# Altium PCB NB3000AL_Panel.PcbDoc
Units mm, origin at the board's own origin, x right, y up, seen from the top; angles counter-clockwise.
Board outline 262 x 196.02 mm, 6 copper layers (Top Layer, GND+SHIELD, MidLayer1, MidLayer2, P2 - 3V3+5V0, Bottom Layer); 0 components, 0 nets, 91 pads, 0 vias.
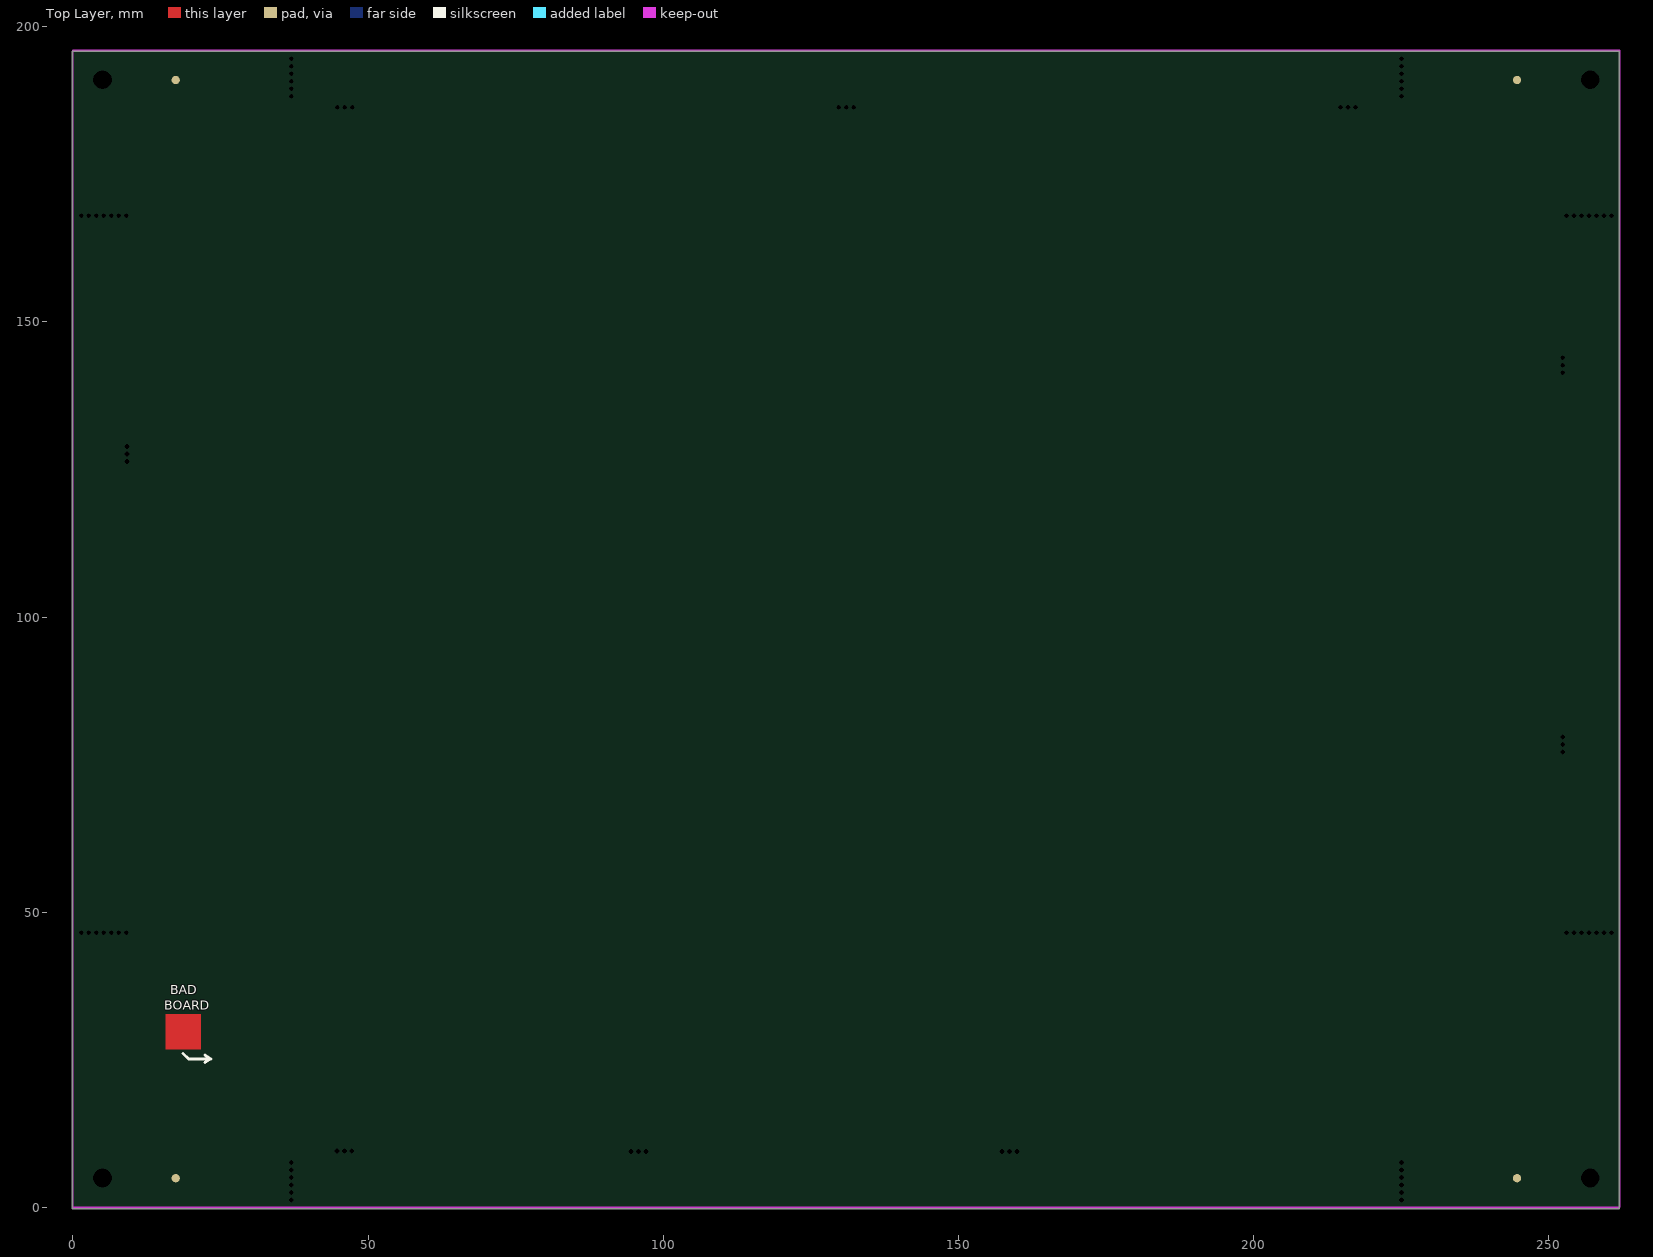
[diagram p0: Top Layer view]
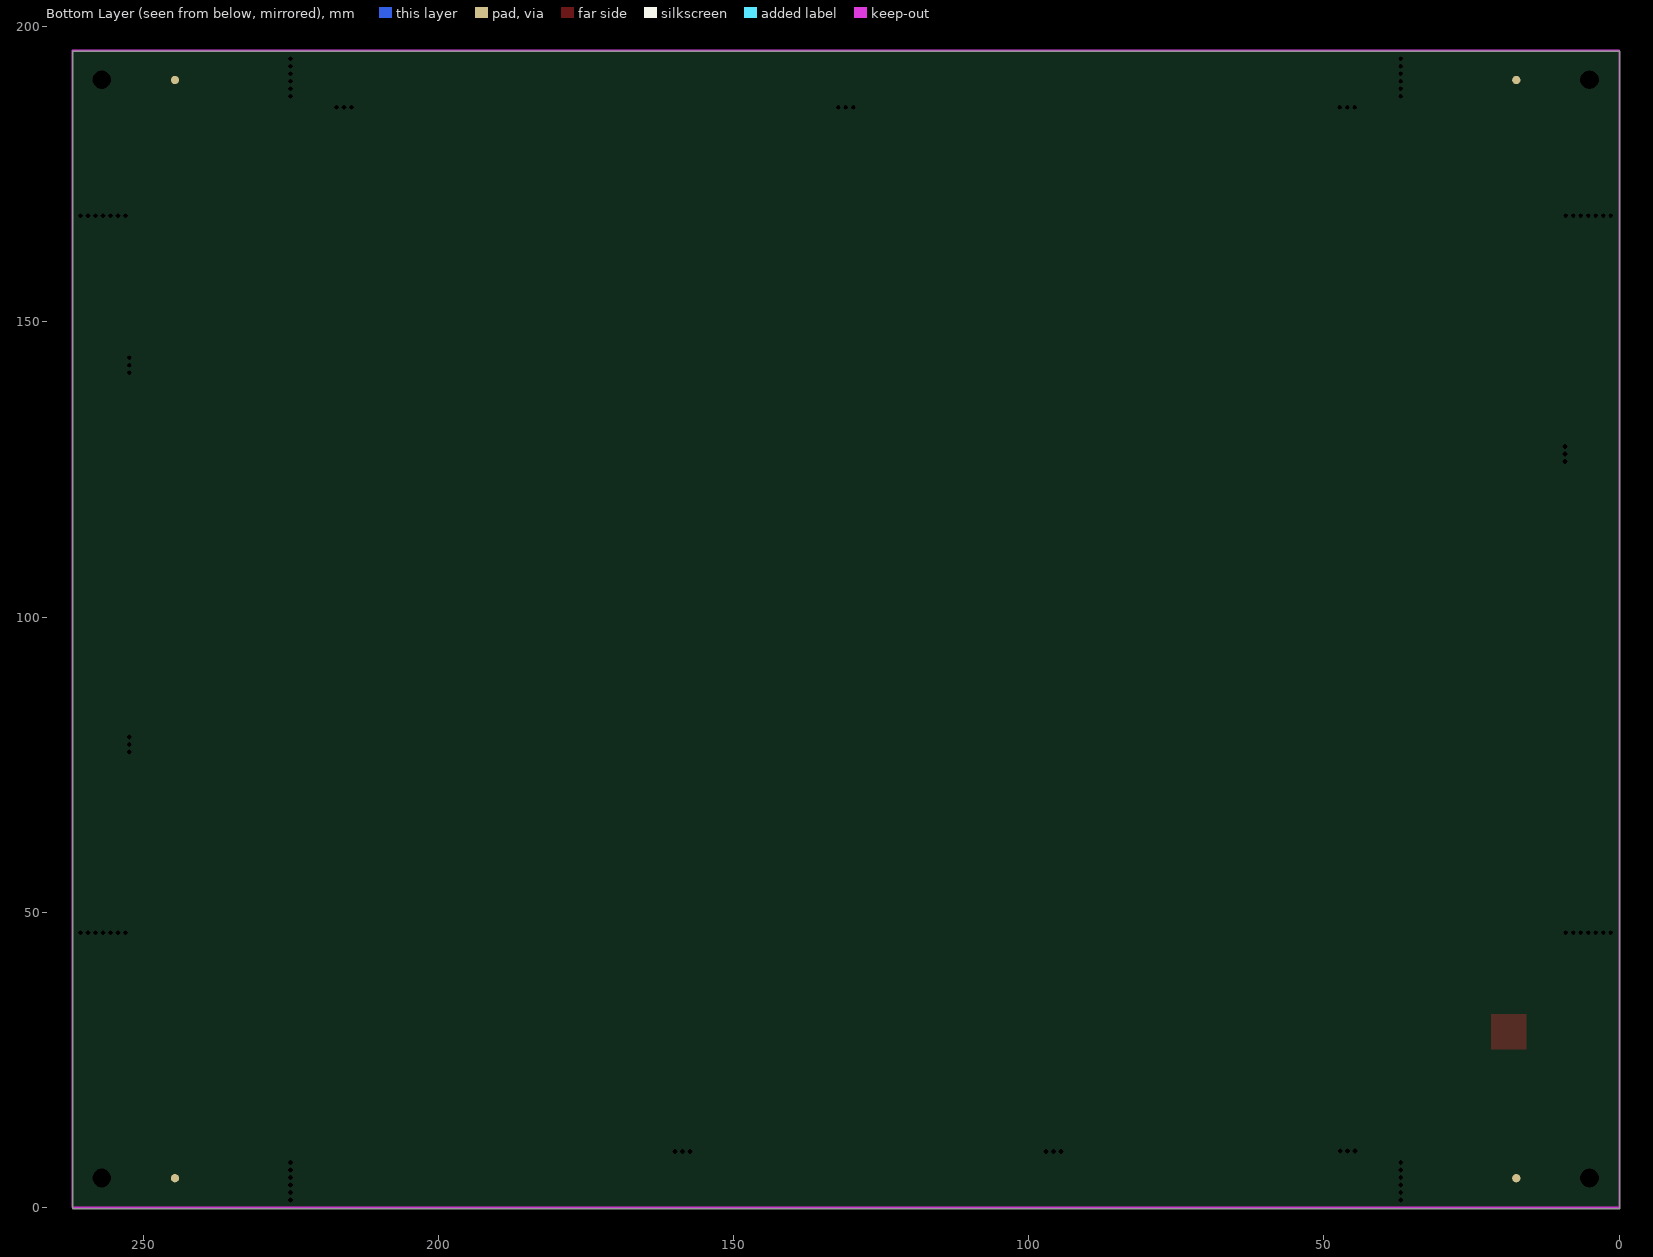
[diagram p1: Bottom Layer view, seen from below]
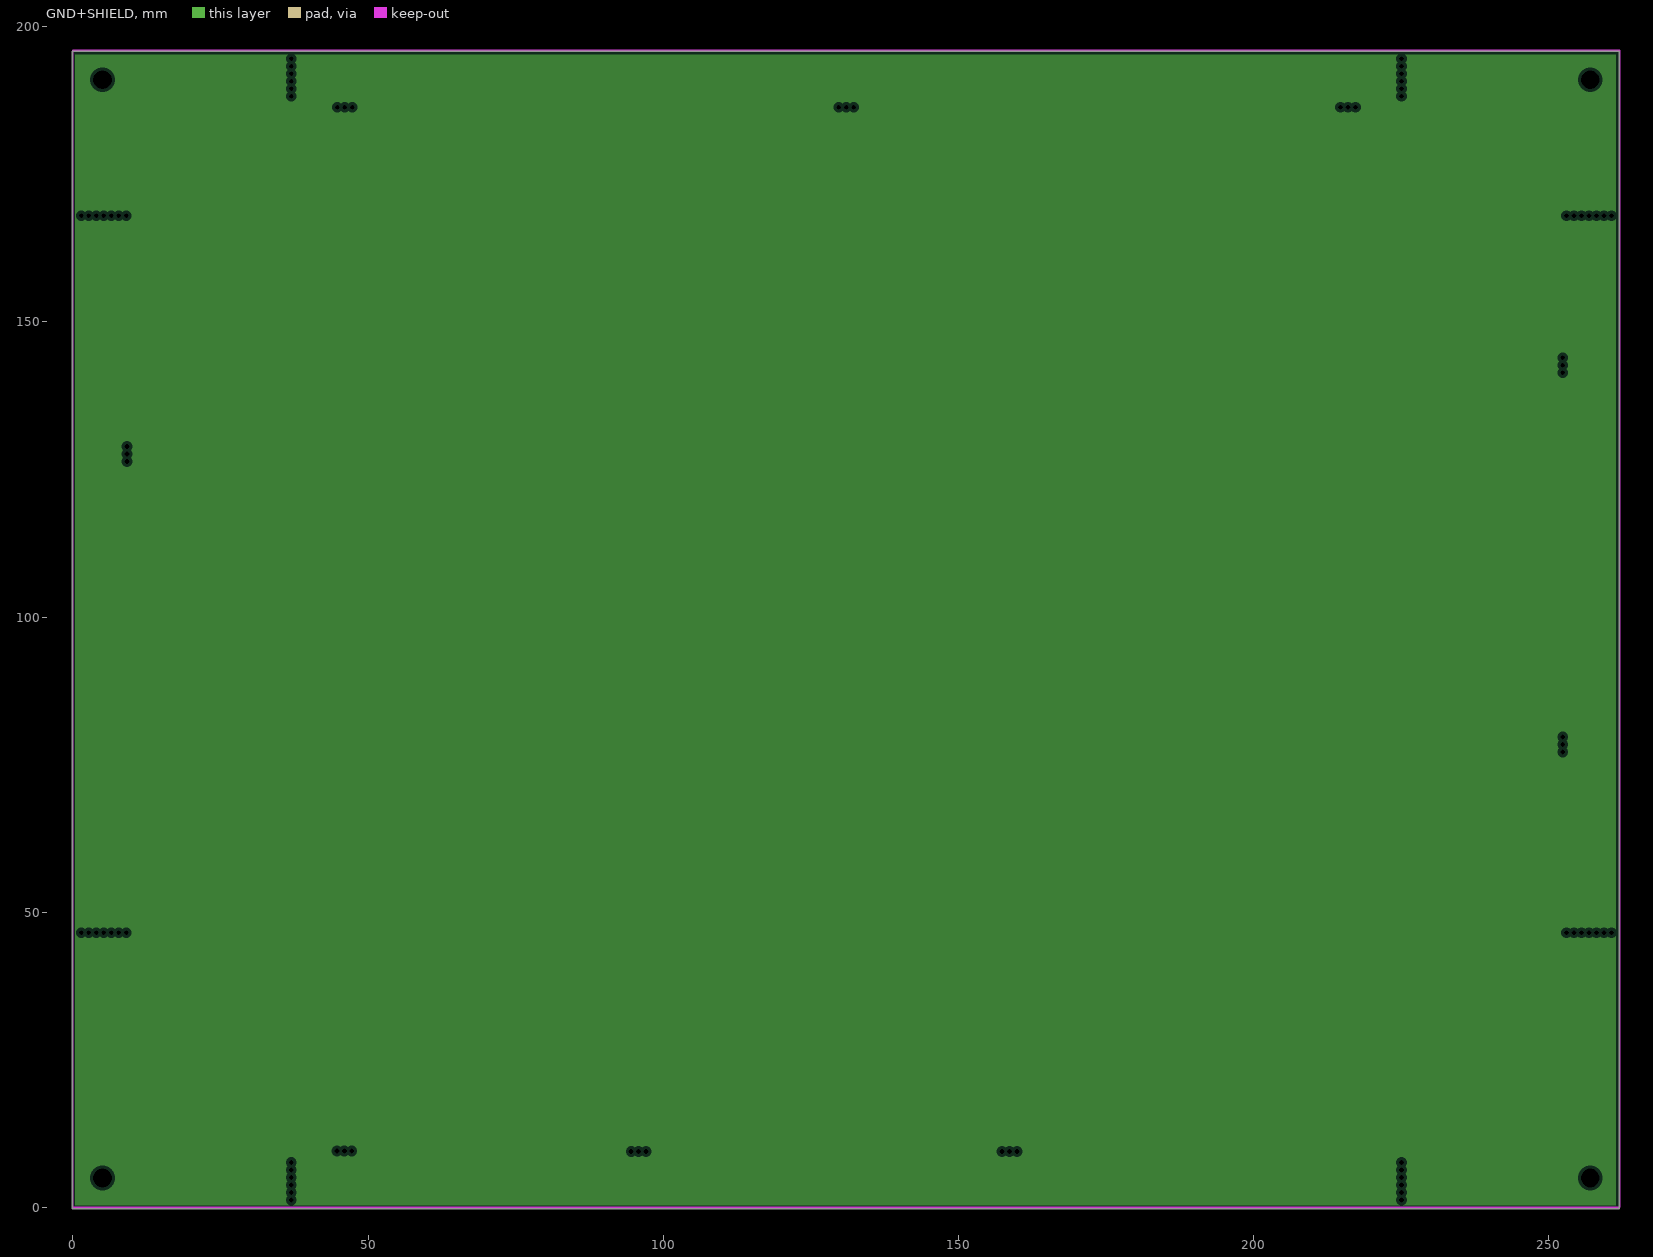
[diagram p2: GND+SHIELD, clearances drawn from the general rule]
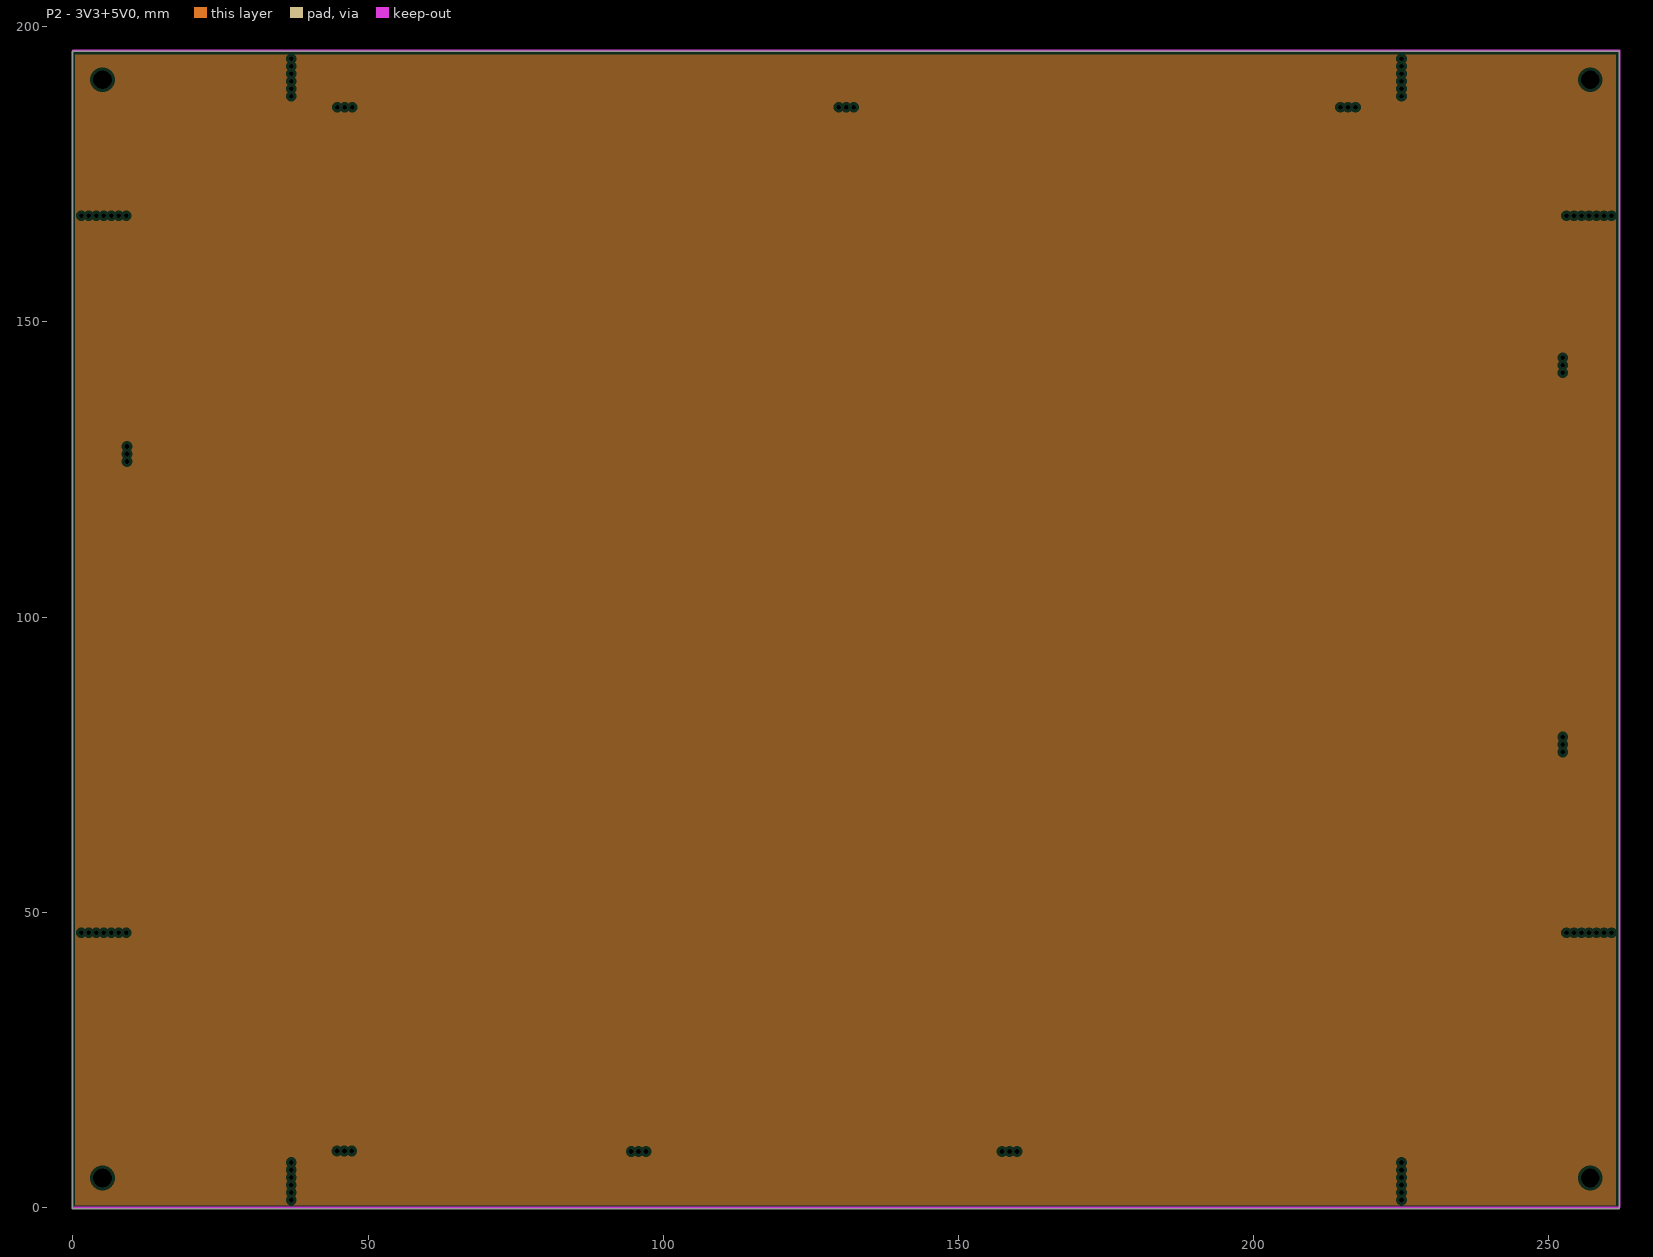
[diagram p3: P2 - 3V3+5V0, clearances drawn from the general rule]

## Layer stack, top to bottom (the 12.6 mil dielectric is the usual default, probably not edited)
Top Layer: signal copper 0.0356
Dielectric: core 0.32, FR-4, Dk 4.8
GND+SHIELD: plane copper 0.0356
Dielectric: prepreg 0.32, FR-4, Dk 4.8
MidLayer1: signal copper 0.0356
Dielectric: core 0.32, FR-4, Dk 4.8
MidLayer2: signal copper 0.0356
Dielectric: prepreg 0.32, FR-4, Dk 4.8
P2 - 3V3+5V0: plane copper 0.0356
Dielectric: core 0.32, FR-4, Dk 4.8
Bottom Layer: signal copper 0.0356

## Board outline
-0.127,-0.178 261.873,-0.178 261.873,195.838 -0.127,195.838

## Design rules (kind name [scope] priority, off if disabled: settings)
Clearance [All] p1: gap=0.254
PlaneClearance [All] p1: clearance=0.508
PlaneConnect [All] p1: planeconnectstyle=Relief reliefexpansion=0.508 reliefentries=4 reliefconductorwidth=0.254 reliefairgap=0.254
PolygonConnect [All] p1: connectstyle=Relief reliefconductorwidth=0.254 reliefentries=4 polygonreliefangle="90 Angle"
RoutingVias [All] p1: holewidth=0.711 width=1.27 viastyle="Through Hole" minholewidth=0.711 minwidth=1.27 maxholewidth=0.711 maxwidth=1.27
SilkscreenOverComponentPads [All] p1: minsilkscreentomaskgap=0.254
SolderMaskExpansion [All] p1: expansion=0.102
TestPointUsage [All] p1: valid=0 allowmultiple=FALSE
Testpoint [All] p1: side=3 testpointundercomponent=TRUE minsize=1.016 maxsize=2.54 preferedsize=1.524 minholesize=0 maxholesize=1.016 preferedholesize=0.813 testpointgrid=0.025 style=297 order=0123456789
Width [All] p1: maxlimit=0.254 minlimit=0.254 preferedwidth=0.254
21 further rules are at their usual default settings.

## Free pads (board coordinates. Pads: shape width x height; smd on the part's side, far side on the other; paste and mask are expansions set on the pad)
  round 2.692 hole 3.2 unplated mask+0.889: 126N(5,5) 126N(5,191.016) 126N(257,5) 126N(257,191.016)
  round 1.397 smd far side paste-2.54 mask+1.321: fidbot(17.4,4.953) fidbot(17.4,190.969) fidbot(244.6,4.953) fidbot(244.6,190.969)
  round 1.397 smd paste-2.54 mask+1.321: fidtop(17.4,4.953) fidtop(17.4,190.969) fidtop(244.6,4.953) fidtop(244.6,190.969)
  round 0.203 hole 0.8 unplated: Snapoff(1.407,46.52) Snapoff(1.422,167.983) Snapoff(2.677,46.52) Snapoff(2.692,167.983) Snapoff(3.947,46.52) Snapoff(3.962,167.983) Snapoff(5.217,46.52) Snapoff(5.232,167.983) Snapoff(6.487,46.52) Snapoff(6.502,167.983) Snapoff(7.757,46.52) Snapoff(7.772,167.983) Snapoff(9.027,46.52) Snapoff(9.042,167.983) Snapoff(9.159,127.635) Snapoff(9.159,128.905) Snapoff(9.159,126.365) Snapoff(36.982,1.275) Snapoff(36.982,2.545) Snapoff(36.982,3.815) Snapoff(36.982,5.085) Snapoff(36.982,6.355) Snapoff(36.982,7.625) Snapoff(36.982,188.219) Snapoff(36.982,189.489) Snapoff(36.982,190.759) Snapoff(36.982,192.029) Snapoff(36.982,193.299) Snapoff(36.982,194.569) Snapoff(44.704,9.563) Snapoff(44.78,186.373) Snapoff(45.974,9.563) Snapoff(46.05,186.372) Snapoff(47.244,9.563) Snapoff(47.32,186.372) Snapoff(94.539,9.487) Snapoff(95.809,9.487) Snapoff(97.079,9.487) Snapoff(129.705,186.372) Snapoff(130.975,186.372) Snapoff(132.245,186.373) Snapoff(157.353,9.487) Snapoff(158.623,9.487) Snapoff(159.893,9.487) Snapoff(214.681,186.373) Snapoff(215.951,186.373) Snapoff(217.221,186.373) Snapoff(225.019,1.275) Snapoff(225.019,2.545) Snapoff(225.019,3.815) Snapoff(225.019,5.085) Snapoff(225.019,6.355) Snapoff(225.019,7.625) Snapoff(225.019,188.219) Snapoff(225.019,189.489) Snapoff(225.019,190.759) Snapoff(225.019,192.029) Snapoff(225.019,193.299) Snapoff(225.019,194.569) Snapoff(252.334,142.646) Snapoff(252.334,143.916) Snapoff(252.334,141.376) Snapoff(252.349,78.432) Snapoff(252.349,79.702) Snapoff(252.349,77.162) Snapoff(252.959,167.983) Snapoff(252.974,46.52) Snapoff(254.229,167.983) Snapoff(254.244,46.52) Snapoff(255.499,167.983) Snapoff(255.514,46.52) Snapoff(256.769,167.983) Snapoff(256.784,46.52) Snapoff(258.039,167.983) Snapoff(258.054,46.52) Snapoff(259.309,167.983) Snapoff(259.324,46.52) Snapoff(260.579,167.983) Snapoff(260.594,46.52)

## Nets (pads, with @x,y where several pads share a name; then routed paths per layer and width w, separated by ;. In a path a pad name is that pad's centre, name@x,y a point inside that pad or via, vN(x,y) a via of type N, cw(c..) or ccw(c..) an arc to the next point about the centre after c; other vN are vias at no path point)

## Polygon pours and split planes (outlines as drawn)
no net on GND+SHIELD (split plane): 261.363,0.333 0.383,0.333 0.383,195.328 261.363,195.328
no net on P2 - 3V3+5V0 (split plane): 261.363,0.333 0.383,0.333 0.383,195.328 261.363,195.328

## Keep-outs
Keep-Out Layer:
  lines w0.254: 0,0 262,0 262,196.016 0,196.016 0,0

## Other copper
Top Layer:
  rectangle: 15.653,26.786 21.653,32.786

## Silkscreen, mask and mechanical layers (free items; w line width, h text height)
Top Overlay:
  lines w0.508: 19.553,25.186 23.353,25.186 ; 19.553,25.186 18.653,26.086 19.553,25.186 ; 19.553,25.186 23.353,25.186 ; 23.353,25.186 22.353,25.786 23.353,25.186 ; 23.353,25.186 22.353,24.586 23.353,25.186
  text "BAD" at 16.452,36.086 h1.52
  text "BOARD" at 15.452,33.486 h1.52
Top Solder:
  rectangle: 15.653,26.786 21.652,32.786
Fab Note:
  drawing of 780 lines, arcs and shapes, not listed
  text "LAYER STACK CONFIGURATION" at 105.029,266.776 h3
  text "6 LAYER BUILD" at 130.02,263.745 h1.25
  text "L1--1 oz" at 152.679,252.324 h0.75
  text "TOP LAYER" at 138.702,252.203 h1.25
  text "-  CORE (0.009\")" at 177.714,250.763 h0.75
  text "L1  - Top Layer (Differential 90 OHM controlled impedance)" at 83.998,250.749 h1
  text "PLANE 1 (GND+SHIELD)" at 130.581,248.514 h1.25
  text "L2--1 oz" at 152.568,248.477 h0.75
  text "-  PRE-PREG (2116X1 --4.2mil)" at 177.614,247.263 h0.75
  text "L3--1 oz" at 152.679,245.974 h0.75
  text "MID LAYER 1" at 139.102,245.103 h1.25
  text "-  CORE (0.026\")" at 177.614,244.163 h0.75
  text "L4--1 oz" at 152.568,242.127 h0.75
  text "MID LAYER 2" at 139.302,242.103 h1.25
  text "-  PRE-PREG (2116X1 --4.2mil)" at 177.614,240.763 h0.75
  text "L5--1 oz" at 152.679,239.116 h0.75
  text "PLANE 2 (3V3+5V0)" at 132.359,238.608 h1.25
  text "-  CORE (0.009\")" at 177.614,237.763 h0.75
  text "L6--1 oz" at 152.568,235.269 h0.75
  text "BOTTOM LAYER" at 137.693,235.052 h1.25
  text "1.6mm" at 171.565,213.878 h1.25
  text "TOTAL BOARD THICKNESS: APPROX" at 139.025,213.729 h1.25
  text "(62mil)" at 178.325,213.729 h1.25
  text "NB3000 PANEL" at 352.55,196.21 h1.25
  text "DESIGN INFORMATION" at 296.311,196.191 h1.25
  text "BOARD NAME:" at 333.903,196.191 h1.25
  text "BOARD TECHNOLOGY" at 296.311,193.651 h1.25
  text "BOARD SIZE (REFER ALSO PROFILING INFORMATION)" at 344.571,193.651 h1.25
  text "4mil" at 298.432,191.462 h1.25
  text "19mil" at 312.11,191.289 h1.25
  text "(mm)" at 384.785,191.211 h1.25
  text "4mil" at 326.08,191.162 h1.25
  text "262.00" at 351.968,191.084 h1.25
  text "196.0162" at 372.034,191.084 h1.25
  text "X" at 363.24,190.603 h1.25
  text "(MIN. TRACK/   PADS  /   CLEARANCE  IN 0.001'')" at 294.787,188.571 h1.25
  text "MINIMUM ANNULAR RING 0.05MM (0.002'') EXTERNAL PER IPC-2221 CLASS 3 LEVEL C AND IS THE" at 296.311,186.031 h1.25
  text "MANUFACTURING REGISTRATION ALLOWANCE" at 296.311,183.745 h1.25
  text "LAND SIZE CALCULATION MINIMUM - NOMINAL HOLE SIZE + 0.508MM (0.020'')" at 296.311,180.951 h1.25
  text "6" at 389.809,176.448 h1.25
  text "CIRCUIT TYPE:" at 296.311,176.379 h1.25
  text "SS" at 319.171,176.379 h1.25
  text "DS" at 336.951,176.379 h1.25
  text "X" at 351.556,176.379 h1.25
  text "PTH" at 354.731,176.379 h1.25
  text "ML" at 365.653,176.379 h1.25
  text "X" at 369.463,176.379 h1.25
  text "No. of Layers" at 372.511,176.379 h1.25
  text "FINGER CONNECTOR DIM PER:" at 296.311,173.331 h1.25
  text "AS SHOWN" at 372.511,173.331 h1.25
  text "No. OFF TOTAL" at 313.075,170.537 h1.25
  text "ONE SIDE" at 354.731,170.537 h1.25
  text "BOTH SIDES" at 372.511,170.283 h1.25
  text "X" at 333.823,167.716 h1.25
  text "VIAS:" at 296.311,167.616 h1.25
  text "NONE" at 307.741,167.616 h1.25
  text "FEED THRU'" at 319.171,167.616 h1.25
  text "TENTED" at 336.951,167.616 h1.25
  text "BURIED LAYER SEQUENCE" at 354.731,167.616 h1.25
  text "UNIQUE DRILL" at 319.171,164.568 h1.25
  text "2 SIZE" at 336.951,164.568 h1.25
  text "BLIND LAYER SEQUENCE" at 354.731,164.568 h1.25
  text "Layer Stack Manager (PCB)" at 331.744,162.282 h1.25
  text "X" at 369.463,162.282 h1.25
  text "AS SHOWN" at 372.511,162.282 h1.25
  text "LAYER CONSTRUCTION PER:" at 296.311,162.155 h1.25
  text "Altium Designer 6.8" at 372.35,159.495 h1.25
  text "ARTWORK:" at 296.311,159.361 h1.25
  text "MANUAL" at 319.171,159.361 h1.25
  text "DIGITISED" at 336.951,159.361 h1.25
  text "X" at 351.683,159.361 h1.25
  text "CAD" at 354.731,159.361 h1.25
  text "TYPE" at 365.653,159.361 h1.25
  text "ARTWORK/PATTERN MASTER LIST" at 296.311,154.662 h1.25
  text "DESCRIPTION" at 297.581,152.249 h1.25
  text "DRAWING No./CAD FILE REF." at 316.25,152.249 h1.25
  text "LAYER NAME" at 357.525,152.249 h1.25
  text "GERBER FILE REF" at 378.277,152.173 h1.25
  text "PCB FILE" at 296.057,149.709 h1.25
  text "2x2 Peripheral Panel" at 316.416,149.651 h1.25
  text "PcbDoc" at 347.67,149.633 h1.25
  text "Top Paste Mask" at 355.849,147.169 h1.25
  text "GTP" at 348.849,147.12 h1.25
  text "GTP" at 398.47,147.093 h1.25
  text "GERBER FILE" at 296.057,147.042 h1.25
  text "GTO" at 348.849,144.62 h1.25
  text "GTO" at 398.419,144.604 h1.25
  text "Top Overlay" at 355.849,144.578 h1.25
  text "GERBER FILE" at 296.057,144.502 h1.25
  text "Top Solder Mask" at 355.849,142.14 h1.25
  text "GTS" at 348.849,142.12 h1.25
  text "GTS" at 398.47,142.013 h1.25
  text "GERBER FILE" at 296.057,141.962 h1.25
  text "Board Layer 1" at 378.209,139.648 h1.25
  text "Top Layer" at 355.849,139.549 h1.25
  text "GTL" at 398.47,139.473 h1.25
  text "GERBER FILE" at 296.057,139.422 h1.25
  text "GTL" at 348.849,139.42 h1.25
  text "Board Layer 2" at 378.177,137.19 h1.25
  text "GP1" at 398.509,137.048 h1.25
  text "GP1" at 348.809,136.948 h1.25
  text "GND+SHIELD" at 356.209,136.948 h1.25
  text "GERBER FILE" at 296.057,136.942 h1.25
  text "Board Layer 3" at 378.177,134.69 h1.25
  text "Mid Layer 1" at 356.077,134.49 h1.25
  text "G1" at 348.809,134.448 h1.25
  text "G1" at 398.509,134.448 h1.25
  text "GERBER FILE" at 296.057,134.402 h1.25
  text "Board Layer 4" at 378.077,132.09 h1.25
  text "G2" at 348.809,131.948 h1.25
  text "G2" at 398.509,131.948 h1.25
  text "Mid Layer 2" at 356.077,131.89 h1.25
  text "GERBER FILE" at 296.057,131.862 h1.25
  text "Board Layer 5" at 378.109,129.648 h1.25
  text "GP2" at 348.809,129.448 h1.25
  text "GP2" at 398.509,129.448 h1.25
  text "3V3+5V0" at 355.776,129.391 h1.25
  text "GERBER FILE" at 296.057,129.322 h1.25
  text "BOTTOM LAYER" at 355.922,126.889 h1.25
  text "Board Layer 6" at 378.163,126.908 h1.25
  text "GBL" at 348.922,126.816 h1.25
  text "GBL" at 398.543,126.813 h1.25
  text "GERBER FILE" at 296.057,126.742 h1.25
  text "GBS" at 348.922,124.416 h1.25
  text "Bottom Solder Mask" at 355.922,124.4 h1.25
  text "GBS" at 398.543,124.273 h1.25
  text "GERBER FILE" at 296.057,124.202 h1.25
  text "GBO" at 348.922,121.816 h1.25
  text "Bottom Overlay" at 355.922,121.809 h1.25
  text "GBO" at 398.543,121.733 h1.25
  text "GERBER FILE" at 296.057,121.662 h1.25
  text "GBP" at 398.543,119.32 h1.25
  text "Bottom Paste Mask" at 355.922,119.269 h1.25
  text "GBP" at 348.922,119.22 h1.25
  text "GERBER FILE" at 296.057,119.122 h1.25
  text "GERBER FILE" at 296.057,116.642 h1.25
  text "GERBER FILE" at 296.057,114.102 h1.25
  text "GERBER FILE" at 296.057,111.562 h1.25
  text "GERBER FILE" at 296.057,109.022 h1.25
  text "APERTURE LIST" at 296.057,103.995 h1.25
  text "APR" at 348.67,103.919 h1.25
  text "DRILL REPORT" at 296.057,101.455 h1.25
  text "DRR" at 348.67,101.379 h1.25
  text "DRILL FILE" at 295.791,98.848 h1.25
  text "DRL" at 348.545,98.704 h1.25
  text "TXT" at 348.391,96.298 h1.25
  text "EXCELLON DRILL" at 295.716,96.223 h1.25
  text "MATERIAL:" at 296.311,91.018 h1.25
  text "GLASS FIBRE EPOXY RESIN NEMA GRADE FR4-08 (IPC-4101) - WITH TG170" at 321.965,90.764 h1.25
  text "X" at 319.298,90.637 h1.25
  text "THICKNESS:" at 304.185,87.843 h1.25
  text "0.8mm" at 321.965,87.843 h1.25
  text "1.2mm" at 339.618,87.843 h1.25
  text "1.6mm" at 357.27,87.844 h1.25
  text "2.4mm" at 375.051,87.843 h1.25
  text "3.2mm" at 392.831,87.843 h1.25
  text "X" at 354.858,87.716 h1.25
  text "2" at 351.009,84.948 h1.25
  text "TOLERANCE:" at 304.058,84.795 h1.25
  text "OTHER +/-" at 375.051,84.795 h1.25
  text "X" at 319.298,84.668 h1.25
  text "IN A/W IPC-D-300G CLASS" at 322.511,84.595 h1.25
  text "2" at 351.009,81.848 h1.25
  text "BOW & TWIST:" at 304.045,81.747 h1.25
  text "AS SHOWN" at 375.178,81.62 h1.25
  text "IN A/W IPC-D-300G CLASS" at 322.511,81.547 h1.25
  text "X" at 319.298,81.493 h1.25
  text "COPPER THICKNESS (FINISHED)" at 301.609,78.748 h1.25
  text "18um" at 321.965,76.159 h1.25
  text "35um" at 349.016,76.159 h1.25
  text "70um" at 375.305,76.159 h1.25
  text "OUTER:" at 305.209,76.048 h1.25
  text "X" at 346.273,75.956 h1.25
  text "INNER SIGNAL:" at 301.609,73.248 h1.25
  text "18um" at 321.965,73.111 h1.25
  text "35um" at 349.016,73.111 h1.25
  text "70um" at 375.305,73.111 h1.25
  text "X" at 346.405,73.025 h1.25
  text "INNER PWR:" at 305.209,70.048 h1.25
  text "18um" at 321.965,70.063 h1.25
  text "35um" at 349.016,70.063 h1.25
  text "70um" at 375.305,70.063 h1.25
  text "X" at 346.405,70.028 h1.25
  text "STRUCTURE:" at 296.311,67.015 h1.25
  text "REFER" at 321.965,67.015 h1.25
  text "AS PER DRAWING No." at 321.838,63.84 h1.25
  text "AS SHOWN" at 375.178,63.84 h1.25
  text "X" at 372.638,63.713 h1.25
  text "DRILLING:" at 296.311,61.046 h1.25
  text "COMPONENT SIDE" at 321.965,58.76 h1.25
  text "SOLDER SIDE" at 348.762,58.76 h1.25
  text "VIEWED FROM:" at 303.309,58.548 h1.25
  text "X" at 319.298,58.506 h1.25
  text "REFERENCE:" at 303.55,55.712 h1.25
  text "AS SHOWN" at 321.838,55.585 h1.25
  text "PATTERN MASTER LIST" at 348.889,55.585 h1.25
  text "X" at 372.638,55.585 h1.25
  text "NC_DRILL FILES" at 375.178,55.585 h1.25
  text "X" at 319.298,55.458 h1.25
  text "20um" at 349.016,52.664 h1.25
  text "PTH MINIMUM COPPER THICKNESS:" at 303.609,52.548 h1.25
  text "X" at 346.349,52.537 h1.25
  text "OTHER" at 375.178,52.537 h1.25
  text "NPTH:" at 303.509,49.648 h1.25
  text "TENTED" at 321.838,49.489 h1.25
  text "X" at 346.349,49.489 h1.25
  text "PADS REMOVED" at 348.889,49.489 h1.25
  text "REMOVE PADS" at 375.178,49.489 h1.25
  text "X" at 319.298,49.362 h1.25
  text "2nd DRILL" at 321.838,46.441 h1.25
  text "BOTH" at 348.889,46.441 h1.25
  text "AS SHOWN" at 361.208,46.441 h1.25
  text "NONE" at 375.178,46.441 h1.25
  text "BOARD FINISH:" at 296.311,43.52 h1.25
  text "X" at 319.298,43.393 h1.25
  text "ETCHING" at 321.838,43.393 h1.25
  text "REFER PATTERN MASTER LIST" at 348.889,43.393 h1.25
  text "NONE" at 330.311,40.456 h1.25
  text "LEGEND / SCREEN PRINT:" at 302.709,40.448 h1.25
  text "COMPONENT" at 348.886,40.421 h1.25
  text "SOLDER" at 375.211,40.356 h1.25
  text "X" at 346.346,40.294 h1.25
  text "X" at 372.671,40.229 h1.25
  text "WHITE" at 321.911,37.556 h1.25
  text "COLOUR:" at 308.609,37.448 h1.25
  text "X" at 319.371,37.429 h1.25
  text "YELLOW" at 348.889,37.297 h1.25
  text "OTHER" at 375.178,37.297 h1.25
  text "SOLDER RESIST:" at 302.509,34.248 h1.25
  text "X" at 319.298,34.249 h1.25
  text "LIQUID PHOTOIMAGEABLE" at 321.838,34.249 h1.25
  text "SCREEN PRINT" at 361.208,34.249 h1.25
  text "FINISH:" at 308.909,31.248 h1.25
  text "MATTE" at 321.838,31.201 h1.25
  text "GLOSS" at 334.538,31.201 h1.25
  text "X" at 331.871,31.074 h1.25
  text "COLOUR:" at 308.609,28.248 h1.25
  text "BLACK" at 321.838,28.153 h1.25
  text "GREEN" at 334.538,28.153 h1.25
  text "YELLOW" at 348.889,28.153 h1.25
  text "BLUE" at 361.208,28.153 h1.25
  text "OTHER" at 375.178,28.153 h1.25
  text "X" at 319.171,28.026 h1.25
  text "TRACK FINISH:" at 296.311,25.232 h1.25
  text "SELECTIVE SOLDER (HASL)" at 321.838,25.105 h1.25
  text "REFLOW SOLDER" at 361.208,25.105 h1.25
  text "0.1um - 0.2um ELECTROLESS GOLD OVER 3um NICKEL" at 321.909,22.248 h1.25
  text "X" at 319.309,22.148 h1.25
  text "IMMERSION GOLD" at 321.838,19.009 h1.25
  text "OTHER" at 361.208,19.009 h1.25
  text "EDGE BOARD" at 296.311,16.088 h1.25
  text "1.3um HARD GOLD OVER 5um     NICKEL / TIN-NICKEL" at 321.838,15.961 h1.25
  text "CONTACTS:" at 296.311,13.929 h1.25
  text "HARD FINISH GOLDE PLATE" at 321.838,12.913 h1.25
  text "OTHER" at 361.208,12.913 h1.25
  text "AS SHOWN" at 321.838,9.865 h1.25
  text "REFER" at 361.208,9.865 h1.25
  text "PROFILING:" at 296.311,6.817 h1.25
  text "AS DIMENSIONED, MEASURED AND CUT FROM SPECIFIED DATUM." at 321.838,6.817 h1.25
  text "X" at 319.298,6.69 h1.25
  text "REFER PCB BLANK DWG No." at 321.965,3.896 h1.25
  text "USE PROFILE / ROUTE TAPE SUPPLIED (REFER PATTERN MASTER LIST)" at 321.965,0.848 h1.25
  text "X" at 354.709,-2.152 h1.25
  text "SQUARE CUT" at 321.965,-2.2 h1.25
  text "N.C. ROUTE" at 339.745,-2.2 h1.25
  text "V. SCORE" at 357.525,-2.2 h1.25
  text "BLANK" at 375.305,-2.2 h1.25
  text "ACCEPTABILITY:" at 296.311,-4.867 h1.25
  text "MATERIALS AND WORKMANSHIP FOR ALL PRINTED WIRING BOARDS TO MEET" at 318.536,-4.994 h1.25
  text "OR EXCEED THE REQUIREMENTS OF:" at 318.536,-7.788 h1.25
  text "IPC-6011/12 AND IPC-A-600E" at 322.092,-10.455 h1.25
  text "1" at 357.652,-10.455 h1.25
  text "2" at 366.542,-10.455 h1.25
  text "3" at 375.438,-10.517 h1.25
  text "X" at 363.875,-10.582 h1.25
  text "X" at 319.425,-10.709 h1.25
  text "UL CERTIFICATION" at 322.092,-13.503 h1.25
  text "AUSTEL" at 357.652,-13.503 h1.25
  text "X" at 319.425,-13.63 h1.25
  text ".Printout_Name" at 178.13,-14.63 h1.25
  text "ML-P-55110F GRP" at 321.584,-16.551 h1.25
  text "A" at 339.872,-16.551 h1.25
  text "B" at 348.762,-16.551 h1.25
  text "AS2546" at 357.652,-16.551 h1.25
  text "OTHER" at 375.432,-16.551 h1.25
  text "ADDITIONAL REQUIREMENTS:" at 296.109,-19.852 h1.25
  text "NONE" at 322.058,-22.43 h1.25
  text "SAMPLE PLAN" at 339.838,-22.43 h1.25
  text "MIL-P-55110E SERIAL Nos. PER ORDER" at 359.618,-22.43 h1.25
  text "X" at 319.359,-22.445 h1.25
  text "MICROSECTION:" at 301.309,-22.552 h1.25
  text "NONE" at 322.153,-25.618 h1.25
  text "CERTIFICATION:" at 301.209,-25.752 h1.25
  text "A" at 359.572,-25.851 h1.25
  text "MIL-P-55110E GRP" at 339.728,-25.901 h1.25
  text "B" at 364.938,-25.93 h1.25
  text "1" at 389.638,-26.03 h1.25
  text "2" at 395.004,-26.109 h1.25
  text "3" at 400.504,-26.109 h1.25
  text "IPC CLASS:" at 375.228,-26.201 h1.25
  text "RoHS Compliant" at 322.153,-28.818 h1.25
  text "X" at 319.359,-28.945 h1.25
  text "X" at 337.097,-29.034 h1.25
  text "QUALITY RELEASE REPORT" at 339.728,-29.101 h1.25
  text "OTHER" at 375.332,-29.151 h1.25
  text "NONE" at 322.098,-32.03 h1.25
  text "REQUIRED (100% PADS & NETS)" at 339.878,-32.03 h1.25
  text "PER ORDER" at 375.538,-32.13 h1.25
  text "ELECTRICAL TEST:" at 301.209,-32.152 h1.25
  text "X" at 337.211,-32.157 h1.25
  text "2 SIDES" at 359.254,-35.217 h1.25
  text "MIN. PITCH" at 375.338,-35.217 h1.25
  text "0.6mm" at 388.927,-35.217 h1.25
  text "NONE" at 322.098,-35.23 h1.25
  text "1 SIDE" at 339.751,-35.23 h1.25
  text "SURFACE MOUNT:" at 301.109,-35.352 h1.25
  text "X" at 357.019,-35.42 h1.25
  text "FOIL" at 359.658,-38.37 h1.25
  text "Bottom Overlay" at 388.515,-38.456 h1.25
  text "NONE" at 339.878,-38.47 h1.25
  text "LEGEND" at 368.388,-38.47 h1.25
  text "REFER" at 380.391,-38.47 h1.25
  text "X" at 365.697,-38.509 h1.25
  text "X" at 377.697,-38.509 h1.25
  text "MANUFACTURER'S ID/LOGO:" at 301.109,-38.752 h1.25
  text "NONE" at 359.709,-41.552 h1.25
  text "ISO9001/AS3901" at 339.898,-41.73 h1.25
  text "MANUFACTURER'S ACCREDITATION:" at 301.109,-41.852 h1.25
  text "X" at 337.231,-41.857 h1.25
  text "PACKAGING AND HANDLING:" at 301.109,-44.652 h1.25
  text "REFER" at 359.658,-44.866 h1.25
  text "PER ORDER" at 339.878,-44.966 h1.25
  text "X" at 337.211,-45.22 h1.25
  text "Notes" at 293.509,-52.652 h1.25
  text "1. All dimensions are in mm." at 295.179,-58.482 h1.25
  text "2. The router cutter diameter is 1.2mm." at 294.869,-63.551 h1.25
  text "3. Impedance control traces on Top Layer (90ohm differential) for 8mil trace." at 295.123,-67.869 h1.25
  text "4. This assembly has uninterrupted (no breakouts) plated edges." at 295.275,-72.161 h1.25
  text "5. PCI connector will be chamfered along the edge on each side of the board (as per standard PCI card edge)" at 295.326,-76.784 h1.25
  text "Typ. Board Thickness = 1.6mm +/- 0.10mm" at 308.926,-80.469 h1
  text "1.4mm" at 301.574,-85.242 h1
  text "20 degrees +/- 5 degrees" at 309.601,-85.319 h1
  text "PCI Edge Connector Side View" at 298.628,-89.027 h1
  text "7. This board has unterminated traces originiating from U8." at 295.478,-94.31 h1.25
Route Cutter Tool Detail:
  lines w1.2: 9.413,125.12 9.413,122.261 ccw(c10.471,122.229) 10.44,121.171 ; 9.413,157.797 cw(c10.471,157.829) 10.44,158.887 ; 9.414,130.15 9.414,136.741 9.414,157.797 ; 10.471,121.171 17.831,121.171 17.831,119.909 10.516,119.909 ccw(c10.55,118.791) 9.431,118.758 9.431,108.8 ccw(c10.55,108.767) 10.516,107.649 17.881,107.649 cw(c17.835,107.323) 18.161,107.277 cw(c17.835,107.231) 17.881,106.905 10.516,106.905 ; 10.471,158.888 17.805,158.888 17.805,160.134 ; 10.483,106.905 ccw(c10.516,105.786) 9.398,105.753 9.398,68.78 ccw(c10.517,68.746) 10.483,67.628 ; 10.517,67.627 10.529,67.615 17.882,67.615 17.882,66.365 11.728,66.365 ccw(c11.762,65.246) 10.644,65.213 10.644,53.175 ; 10.643,53.175 10.643,46.394 22.581,46.393 cw(c22.555,36.055) 32.893,36.03 32.893,11.519 ; 10.643,168.11 22.454,168.11 ccw(c22.517,178.486) 32.893,178.422 32.893,184.62 36.033,184.62 ccw(c36.02,184.998) 36.398,185.011 36.398,186.626 43.536,186.626 ; 10.643,168.125 10.643,161.239 ccw(c11.7,161.208) 11.669,160.15 17.805,160.15 ; 32.893,11.392 36.02,11.392 cw(c36.02,11.09) 36.322,11.09 36.322,9.309 43.459,9.309 ; 48.489,9.309 93.193,9.309 ; 48.565,186.626 128.461,186.626 ; 98.439,9.309 155.939,9.309 ; 133.49,186.627 213.436,186.627 ; 161.265,9.309 225.679,9.309 225.679,11.09 cw(c225.981,11.09) 225.981,11.392 228.956,11.392 229.108,11.544 229.108,36.03 cw(c239.446,36.055) 239.42,46.393 251.358,46.393 251.358,53.175 ; 218.465,186.627 225.603,186.627 225.603,185.011 ; 229.108,184.493 229.108,178.422 ccw(c239.484,178.486) 239.547,168.11 251.358,168.11 251.358,161.224 cw(c250.301,161.193) 250.332,160.135 244.196,160.134 244.196,158.888 251.53,158.888 ; 229.108,184.62 225.968,184.62 ; 251.357,53.175 251.357,65.213 ccw(c250.239,65.246) 250.273,66.365 244.119,66.365 244.119,67.627 251.484,67.627 ; 251.485,106.905 244.12,106.905 cw(c244.166,107.231) 243.84,107.277 cw(c244.166,107.323) 244.12,107.649 251.485,107.649 ccw(c251.451,108.767) 252.57,108.8 252.57,118.758 ccw(c251.451,118.791) 251.485,119.909 244.17,119.909 244.17,121.171 251.53,121.171 ; 251.518,67.628 ccw(c251.484,68.746) 252.603,68.78 252.603,75.917 ; 251.518,106.905 cw(c251.485,105.786) 252.603,105.753 252.603,80.947 ; 251.561,121.171 ccw(c251.53,122.229) 252.588,122.261 252.588,140.132 ; 251.561,158.887 cw(c251.53,157.829) 252.588,157.797 252.588,145.161 ; 128.461,186.626 128.461,186.626 ; 213.436,186.627 213.436,186.626 ; 225.603,185.011 ccw(c225.981,184.998) 225.968,184.62 ; 225.603,185.011 ccw(c225.981,184.998) 225.968,184.62
  text ".Printout_Name" at 178.213,-17.273 h1.25

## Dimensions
0,0 to 262,0 on Keep-Out Layer
262,196.016 to 262,0 on Keep-Out Layer

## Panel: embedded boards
"NB3000AL.PcbDoc" at 10,10, 1 rows x 1 columns, spacing 203.2 x 152.4, rotation 0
